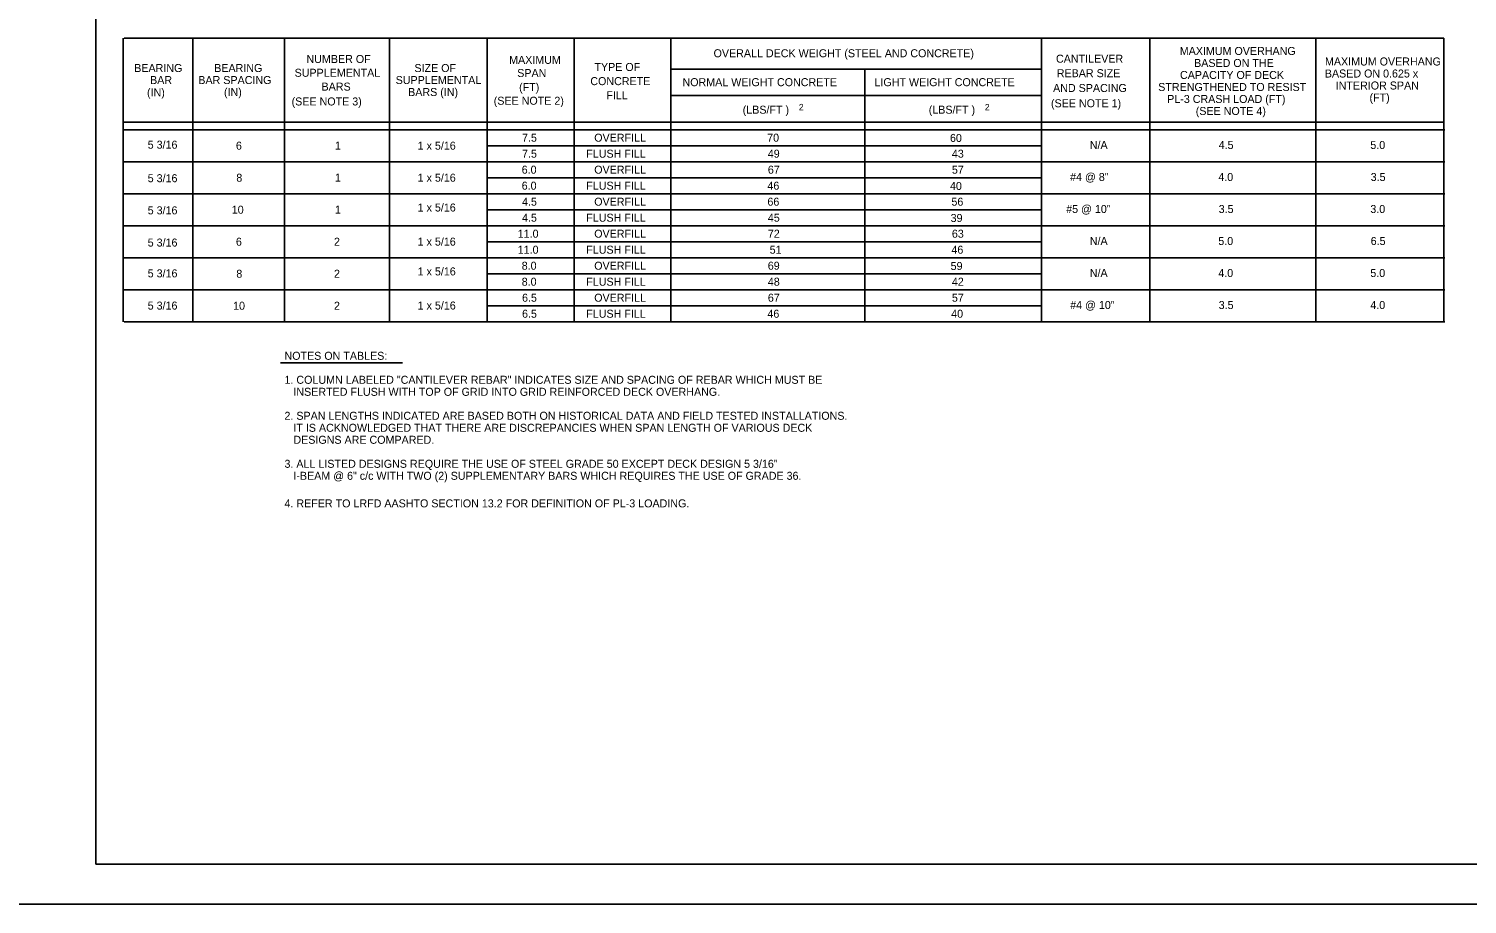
# Model space of a CAD drawing. Extents: x -24512 to -22484, y 4569 to 6351.
# Drawn here: x -23322 to -22783, y 5163 to 5491 of the extents above; entities that cross this region are included whole.
import ezdxf

# ---------------------------------------------------------------- set-up
doc = ezdxf.new("R2010")
doc.units = 0
for name, color, linetype in [('1', 7, 'Continuous'), ('2', 7, 'Continuous'), ('3', 7, 'Continuous'), ('6', 7, 'Continuous'), ('PLT-BNDY', 7, 'Continuous')]:
    doc.layers.add(name, color=color, linetype=linetype)

msp = doc.modelspace()

# ---------------------------------------------------------------- linework, layer by layer
at = {"layer": '2'}
for p, q in [((-23296.79, 5178.04), (-23296.79, 5740.63)), ((-22512.75, 5178.04), (-23296.79, 5178.04))]:
    msp.add_line(p, q, dxfattribs=at)
at = {"layer": '3'}
for p, q in [((-23286.53, 5381.42), (-23286.53, 5487.67)), ((-23286.18, 5487.67), (-22791.35, 5487.67)), ((-23260.41, 5381.42), (-23260.41, 5487.67)), ((-23226.08, 5381.42), (-23226.08, 5487.67)), ((-23186.66, 5381.42), (-23186.66, 5487.67)), ((-23150.09, 5381.42), (-23150.09, 5487.67)), ((-23117.51, 5381.42), (-23117.51, 5487.67)), ((-23081.19, 5381.42), (-23081.19, 5487.67)), ((-22942.27, 5381.42), (-22942.27, 5487.67)), ((-22901.6, 5381.42), (-22901.6, 5487.67)), ((-22839.35, 5381.42), (-22839.35, 5487.67)), ((-22791.35, 5381.42), (-22791.35, 5487.67)), ((-23080.84, 5476.07), (-22942.27, 5476.07)), ((-23008.44, 5381.42), (-23008.44, 5476.07)), ((-22942.27, 5466.27), (-23080.84, 5466.27)), ((-23286.53, 5456.22), (-22791.35, 5456.22)), ((-23286.18, 5453.42), (-22791, 5453.42)), ((-23149.74, 5447.42), (-22942.27, 5447.42)), ((-23286.18, 5441.42), (-23149.74, 5441.42)), ((-23149.68, 5441.42), (-22791, 5441.42)), ((-23149.74, 5435.42), (-22942.27, 5435.42)), ((-23286.18, 5429.42), (-23149.74, 5429.42)), ((-23149.68, 5429.42), (-22791, 5429.42)), ((-23149.74, 5423.42), (-22942.27, 5423.42)), ((-23286.18, 5417.42), (-23149.74, 5417.42)), ((-23149.68, 5417.42), (-22791, 5417.42)), ((-23149.74, 5411.42), (-22942.27, 5411.42)), ((-23286.18, 5405.42), (-23149.74, 5405.42)), ((-23149.68, 5405.42), (-22791, 5405.42)), ((-23149.74, 5399.42), (-22942.27, 5399.42)), ((-23286.18, 5393.42), (-23149.74, 5393.42)), ((-23149.68, 5393.42), (-22791, 5393.42)), ((-23149.74, 5387.42), (-22942.27, 5387.42)), ((-23286.18, 5381.42), (-22791, 5381.42))]:
    msp.add_line(p, q, dxfattribs=at)
at = {"layer": '6'}
msp.add_line((-23227.53, 5365.98), (-23181.88, 5365.98), dxfattribs=at)
at = {"layer": 'PLT-BNDY'}
msp.add_lwpolyline([(-23338.75, 5757.04), (-22497.75, 5757.04), (-22497.75, 5163.04), (-23338.75, 5163.04)], close=True, dxfattribs=at)

# ---------------------------------------------------------------- texts
at = {"layer": '1'}
for s, p in [('MAXIMUM OVERHANG', (-22890.39, 5481.43)), ('BASED ON THE', (-22885.02, 5476.93)), ('MAXIMUM OVERHANG', (-22835.95, 5477.48)), ('CAPACITY OF DECK', (-22890.31, 5472.43)), ('BASED ON 0.625 x', (-22836.01, 5472.98)), ('STRENGTHENED TO RESIST', (-22898.47, 5467.93)), ('INTERIOR SPAN', (-22831.93, 5468.48)), ('PL-3 CRASH LOAD (FT)', (-22895.12, 5463.43)), ('(FT)', (-22819.25, 5463.98)), ('(SEE NOTE 4)', (-22884.4, 5458.93)), ('4.5', (-22875.81, 5446.19)), ('5.0', (-22818.94, 5446.19)), ('4.0', (-22875.94, 5434.19)), ('3.5', (-22818.81, 5434.19)), ('3.5', (-22875.81, 5422.19)), ('3.0', (-22818.94, 5422.19)), ('5.0', (-22875.94, 5410.19)), ('6.5', (-22818.81, 5410.19)), ('4.0', (-22875.94, 5398.19)), ('5.0', (-22818.94, 5398.19)), ('3.5', (-22875.81, 5386.19)), ('4.0', (-22818.94, 5386.19))]:
    msp.add_text(s, height=3, dxfattribs=at).set_placement(p)
at = {"layer": '6'}
for s, height, p in [('NUMBER OF', 3, (-23217.83, 5478.42)), ('MAXIMUM', 3, (-23141.84, 5478.09)), ('OVERALL DECK WEIGHT (STEEL AND CONCRETE)', 2.9998, (-23065.19, 5480.57)), ('CANTILEVER', 3, (-22936.8, 5478.53)), ('BEARING', 3, (-23282.42, 5475.03)), ('BEARING', 3, (-23252.43, 5475.03)), ('SUPPLEMENTAL', 2.9998, (-23222.28, 5473.26)), ('SIZE OF', 3, (-23177.36, 5475.03)), ('SPAN', 3, (-23138.81, 5473.15)), ('TYPE OF', 3, (-23109.86, 5475.43)), ('REBAR SIZE', 3, (-22936.51, 5473.1)), ('(IN)', 3, (-23277.62, 5465.89)), ('BAR', 3, (-23276.47, 5470.53)), ('BAR SPACING', 2.9998, (-23258.38, 5470.53)), ('(IN)', 3, (-23248.76, 5466.03)), ('BARS', 3, (-23212.18, 5468.07)), ('SUPPLEMENTAL', 2.9998, (-23184.39, 5470.53)), ('BARS (IN)', 3, (-23179.71, 5466.03)), ('(FT)', 3, (-23138.11, 5467.87)), ('CONCRETE', 3, (-23111.4, 5470.12)), ('NORMAL WEIGHT CONCRETE', 2.9998, (-23076.85, 5469.73)), ('LIGHT WEIGHT CONCRETE', 2.9998, (-23004.86, 5469.73)), ('AND SPACING', 3, (-22937.89, 5467.55)), ('(SEE NOTE 3)', 3, (-23223.4, 5462.5)), ('(SEE NOTE 2)', 3, (-23147.62, 5462.77)), ('FILL', 3, (-23105.38, 5464.82)), ('(SEE NOTE 1)', 3, (-22938.68, 5461.82)), ('(LBS/FT )', 3, (-23054.27, 5459.41)), ('2', 2.39, (-23033.21, 5460.69)), ('(LBS/FT )', 3, (-22984.51, 5459.41)), ('2', 2.39, (-22963.45, 5460.69)), ('5 3/16', 3, (-23277.36, 5446.29)), ('6', 3, (-23244.29, 5445.92)), ('1', 3, (-23207.18, 5445.92)), ('1 x 5/16', 3, (-23176.14, 5445.92)), ('7.5', 3, (-23137, 5448.91)), ('OVERFILL', 3, (-23109.94, 5448.91)), ('70', 3, (-23045.1, 5448.91)), ('60', 3, (-22976.55, 5448.82)), ('N/A', 3, (-22924.13, 5446.19)), ('7.5', 3, (-23137, 5442.92)), ('FLUSH FILL', 3, (-23112.92, 5442.92)), ('49', 3, (-23044.86, 5442.92)), ('43', 3, (-22975.84, 5442.92)), ('5 3/16', 3, (-23277.36, 5433.72)), ('8', 3, (-23244.13, 5433.92)), ('1', 3, (-23207.18, 5433.92)), ('1 x 5/16', 3, (-23176.14, 5433.92)), ('6.0', 3, (-23137.13, 5436.92)), ('OVERFILL', 3, (-23109.94, 5436.92)), ('67', 3, (-23044.84, 5436.92)), ('57', 3, (-22975.84, 5436.92)), ('#4 @ 8"', 3, (-22931.51, 5434.19)), ('6.0', 3, (-23137.13, 5430.92)), ('FLUSH FILL', 3, (-23112.92, 5430.92)), ('46', 3, (-23045, 5430.92)), ('40', 3, (-22976.55, 5430.82)), ('1 x 5/16', 3, (-23176.14, 5422.74)), ('4.5', 3, (-23137, 5424.92)), ('OVERFILL', 3, (-23109.94, 5424.92)), ('66', 3, (-23045, 5424.92)), ('56', 3, (-22976.01, 5424.92)), ('5 3/16', 3, (-23277.36, 5421.68)), ('10', 3, (-23245.84, 5421.92)), ('1', 3, (-23207.18, 5421.92)), ('4.5', 3, (-23137, 5418.92)), ('FLUSH FILL', 3, (-23112.92, 5418.92)), ('45', 3, (-23044.84, 5418.92)), ('39', 3, (-22976.31, 5418.82)), ('#5 @ 10"', 3, (-22932.98, 5422.19)), ('11.0', 3, (-23138.62, 5412.92)), ('OVERFILL', 3, (-23109.94, 5412.92)), ('72', 3, (-23044.84, 5412.92)), ('63', 3, (-22975.84, 5412.92)), ('5 3/16', 3, (-23277.36, 5409.6)), ('6', 3, (-23244.29, 5409.92)), ('2', 3, (-23207.52, 5409.92)), ('1 x 5/16', 3, (-23176.14, 5409.95)), ('11.0', 3, (-23138.62, 5406.92)), ('FLUSH FILL', 3, (-23112.92, 5406.92)), ('51', 3, (-23044.15, 5406.92)), ('46', 3, (-22976.01, 5406.92)), ('N/A', 3, (-22924.13, 5410.19)), ('5 3/16', 3, (-23277.36, 5398.05)), ('8', 3, (-23244.13, 5397.92)), ('2', 3, (-23207.52, 5397.92)), ('1 x 5/16', 3, (-23176.14, 5398.78)), ('8.0', 3, (-23137.13, 5400.92)), ('OVERFILL', 3, (-23109.94, 5400.92)), ('69', 3, (-23044.86, 5400.92)), ('59', 3, (-22976.31, 5400.82)), ('N/A', 3, (-22924.13, 5398.19)), ('8.0', 3, (-23137.13, 5394.92)), ('FLUSH FILL', 3, (-23112.92, 5394.92)), ('48', 3, (-23044.84, 5394.92)), ('42', 3, (-22975.84, 5394.92)), ('5 3/16', 3, (-23277.36, 5385.97)), ('10', 3, (-23245.34, 5385.92)), ('2', 3, (-23207.52, 5385.92)), ('1 x 5/16', 3, (-23176.14, 5386)), ('6.5', 3, (-23137, 5388.92)), ('OVERFILL', 3, (-23109.94, 5388.92)), ('67', 3, (-23044.84, 5388.92)), ('57', 3, (-22975.84, 5388.92)), ('#4 @ 10"', 3, (-22931.48, 5386.19)), ('6.5', 3, (-23137, 5382.92)), ('FLUSH FILL', 3, (-23112.92, 5382.92)), ('46', 3, (-23045, 5382.92)), ('40', 3, (-22976.1, 5382.92)), ('NOTES ON TABLES:', 2.9998, (-23226.08, 5367.15)), ('1. COLUMN LABELED "CANTILEVER REBAR" INDICATES SIZE AND SPACING OF REBAR WHICH MUST BE', 3, (-23226.08, 5358.15)), ('   INSERTED FLUSH WITH TOP OF GRID INTO GRID REINFORCED DECK OVERHANG.', 2.9998, (-23226.08, 5353.65)), ('2. SPAN LENGTHS INDICATED ARE BASED BOTH ON HISTORICAL DATA AND FIELD TESTED INSTALLATIONS.', 2.9998, (-23226.08, 5344.66)), ('   IT IS ACKNOWLEDGED THAT THERE ARE DISCREPANCIES WHEN SPAN LENGTH OF VARIOUS DECK', 2.9998, (-23226.08, 5340.16)), ('   DESIGNS ARE COMPARED.', 2.9998, (-23226.08, 5335.66)), ('3. ALL LISTED DESIGNS REQUIRE THE USE OF STEEL GRADE 50 EXCEPT DECK DESIGN 5 3/16"', 3, (-23226.08, 5326.66)), ('   I-BEAM @ 6" c/c WITH TWO (2) SUPPLEMENTARY BARS WHICH REQUIRES THE USE OF GRADE 36.', 3, (-23226.08, 5322.16)), ('4. REFER TO LRFD AASHTO SECTION 13.2 FOR DEFINITION OF PL-3 LOADING.', 3, (-23226.08, 5311.82))]:
    msp.add_text(s, height=height, dxfattribs=at).set_placement(p)

doc.saveas('drawing.dxf')
